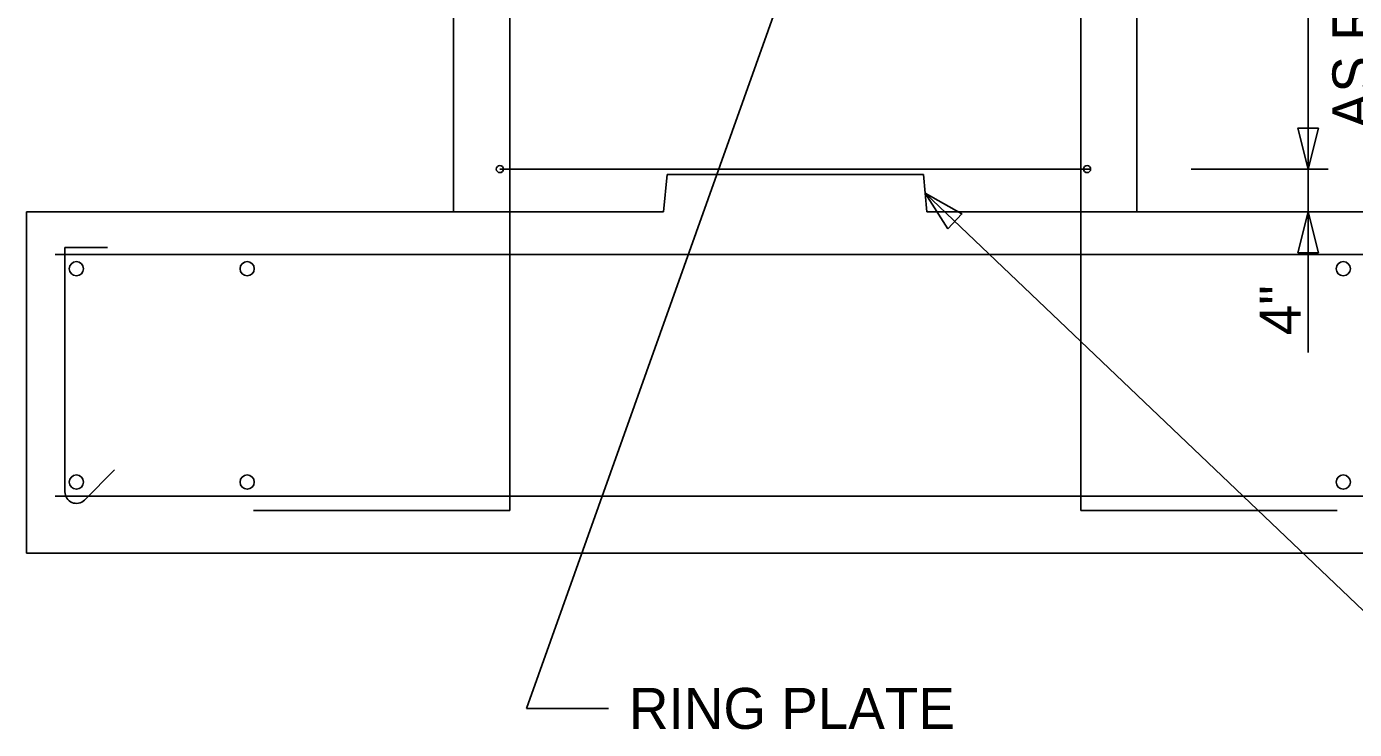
# Model space of a CAD drawing. Extents: x 1299104.6 to 1299141.4, y 239713.3 to 239735.3.
# Drawn here: x 1299109.4 to 1299113.286, y 239717.506 to 239719.565 of the extents above; entities that cross this region are included whole.
import ezdxf

# ---------------------------------------------------------------- set-up
doc = ezdxf.new("R2010")
doc.units = 0
for name, color, linetype in [('DIM TXT', 7, 'Continuous'), ('Level 3', 7, 'Continuous'), ('Level 8', 7, 'Continuous')]:
    doc.layers.add(name, color=color, linetype=linetype)

msp = doc.modelspace()

# ---------------------------------------------------------------- linework, layer by layer
at = {"layer": 'Level 3'}
for p, q in [((1299110.6495, 239719.022), (1299110.6495, 239721.9803)), ((1299112.6495, 239721.9803), (1299112.6495, 239719.022)), ((1299110.8136, 239718.147), (1299110.8136, 239721.9387)), ((1299112.4854, 239718.147), (1299112.4854, 239721.9387)), ((1299112.5141, 239719.147), (1299110.7849, 239719.147)), ((1299111.2745, 239719.1314), (1299111.2641, 239719.022)), ((1299112.0245, 239719.1314), (1299111.2745, 239719.1314)), ((1299112.0349, 239719.022), (1299112.0245, 239719.1314)), ((1299110.8995, 239719.022), (1299109.3995, 239719.022)), ((1299109.3995, 239719.022), (1299109.3995, 239718.022)), ((1299111.2641, 239719.022), (1299110.8995, 239719.022)), ((1299112.3995, 239719.022), (1299112.0349, 239719.022)), ((1299113.8995, 239719.022), (1299112.3995, 239719.022)), ((1299113.8162, 239718.897), (1299109.4828, 239718.897)), ((1299109.5118, 239718.2014), (1299109.5118, 239718.9178)), ((1299109.5118, 239718.9178), (1299109.6368, 239718.9178)), ((1299109.6574, 239718.266), (1299109.5691, 239718.1776)), ((1299113.8162, 239718.1887), (1299109.4828, 239718.1887)), ((1299110.8136, 239718.147), (1299110.0636, 239718.147)), ((1299112.4854, 239718.147), (1299113.2354, 239718.147)), ((1299113.8995, 239718.022), (1299109.3995, 239718.022))]:
    msp.add_line(p, q, dxfattribs=at)
for centre, radius in [((1299110.7849, 239719.147), 0.0104), ((1299112.5037, 239719.147), 0.0104), ((1299109.5453, 239718.8553), 0.0208), ((1299110.0453, 239718.8553), 0.0208), ((1299113.2537, 239718.8553), 0.0208), ((1299109.5453, 239718.2303), 0.0208), ((1299110.0453, 239718.2303), 0.0208), ((1299113.2537, 239718.2303), 0.0208)]:
    msp.add_circle(centre, radius, dxfattribs=at)
msp.add_arc((1299109.5453, 239718.2014), 0.0335, 180, 315, dxfattribs=at)
at = {"layer": 'Level 8'}
for p, q in [((1299113.151, 239722.3405), (1299113.151, 239718.61)), ((1299111.6264, 239719.7098), (1299110.8628, 239717.5674)), ((1299112.8088, 239719.147), (1299113.2096, 239719.147)), ((1299112.0297, 239719.0767), (1299113.6573, 239717.5239)), ((1299111.1028, 239717.5674), (1299110.8628, 239717.5674))]:
    msp.add_line(p, q, dxfattribs=at)
for points in [[(1299113.181, 239719.267), (1299113.151, 239719.147), (1299113.121, 239719.267)], [(1299112.0958, 239718.9721), (1299112.0297, 239719.0767), (1299112.1373, 239719.0155)], [(1299113.181, 239718.902), (1299113.151, 239719.022), (1299113.121, 239718.902)]]:
    msp.add_lwpolyline(points, close=True, dxfattribs=at)

# ---------------------------------------------------------------- texts
at = {"layer": 'DIM TXT'}
for s, p in [('AS REQUIRED BY DESIGN', (1299113.3418, 239719.2638)), ('4"', (1299113.1287, 239718.6606))]:
    msp.add_text(s, height=0.12, rotation=90, dxfattribs=at).set_placement(p)
msp.add_text('RING PLATE', height=0.12, dxfattribs=at).set_placement((1299111.1628, 239717.5074))

doc.saveas('drawing.dxf')
